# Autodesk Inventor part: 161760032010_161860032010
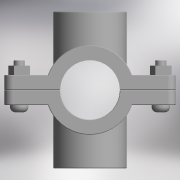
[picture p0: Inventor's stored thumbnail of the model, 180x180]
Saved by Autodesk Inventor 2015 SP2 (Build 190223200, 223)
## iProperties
Created: 2017-05
Part Number: 161760032010_161860032010
Material: Generic
Description: PLASSON DOUBLE SADDLE 32-1"
Document SubType Name: Modeling
Designer: KIM
Density: 1 g/cm^3
Appearance: Default
Author: KIM
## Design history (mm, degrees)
derived "16176.ipt"
feature "Solid1::16176.ipt"
feature "Solid2::16176.ipt"
tag "TaggingFeature1"
body "Solid1"
body "Solid2"
other parameters: "d0" = 48, "d1" = 92, "d2" = 16, "d3" = 32, "d5" = 0, "d6" = 4.6, "d7" = 92, "d8" = 0.1, "d10" = 0, "d11" = 0.32, "d20" = 0.32, "d23" = 0.32, "d37" = 8, "d38" = 24, "d39" = 0, "d40" = 3, "d41" = 5, "d42" = 0, "d43" = 6, "d44" = 3, "d45" = 0, "d46" = 0.32, "d52" = 30.291, "d53" = 21, "d54" = 0, "d57" = 0, "d58" = 34.56, "d60" = 0, "d66" = 0, "d67" = 84, "d68" = 39.3783, "d69" = 30.291, "d70" = 21, "d71" = 0, "d74" = 0, "d75" = 0.32, "d_" = 32, "G_" = 30.291, "A_" = 42, "L_" = 92, "l_2" = 21
